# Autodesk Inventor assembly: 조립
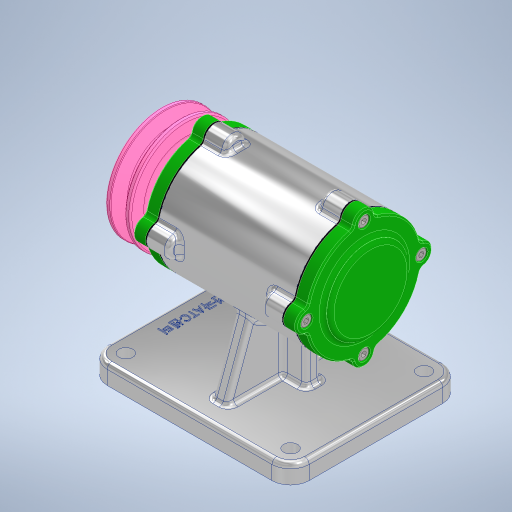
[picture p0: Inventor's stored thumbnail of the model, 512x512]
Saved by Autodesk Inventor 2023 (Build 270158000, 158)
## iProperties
Created: 2023-08
Part Number: 조립
Document SubType Name: Assembly
Designer: asung
Author: asung
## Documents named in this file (12)
- C:\Users\asung\Desktop\730808V1008\조립.iam
- C:\Users\asung\Desktop\730808V1008\본체.ipt
- C:\Users\asung\Desktop\730808V1008\730808V1008\베어링 6204.ipt
- C:\Users\asung\Desktop\730808V1008\730808V1008\앞커버.ipt
- C:\Users\asung\Desktop\730808V1008\730808V1008\개스킷.ipt
- C:\Users\asung\Desktop\730808V1008\730808V1008\축.ipt
- C:\Users\asung\Desktop\730808V1008\730808V1008\뒤커버.ipt
- C:\Users\asung\Desktop\730808V1008\730808V1008\볼트 M4 x 12.ipt
- C:\Users\asung\Desktop\730808V1008\730808V1008\키 4 x 4.ipt
- C:\Users\asung\Desktop\730808V1008\730808V1008\V-벨트풀리.ipt
- C:\Users\asung\Desktop\730808V1008\730808V1008\오일 실.ipt
- C:\Users\asung\Desktop\730808V1008\730808V1008\너트 M12 x 1.25.ipt
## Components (8 placed, 6 different names)
1. KS B 2023 6204 - 20 x 47 x 14:1
2. KS B 2023 6204 - 20 x 47 x 14:2
3. 개스킷:1
4. 개스킷:2
5. KS B 1311 (I) 4 x 4 x 12:1
6. V-벨트풀리:1
7. KS B 2804 D D - 20 32 8:1
8. KS B 1012 클래스 1 일반 - 미터 M12x1.25:1
